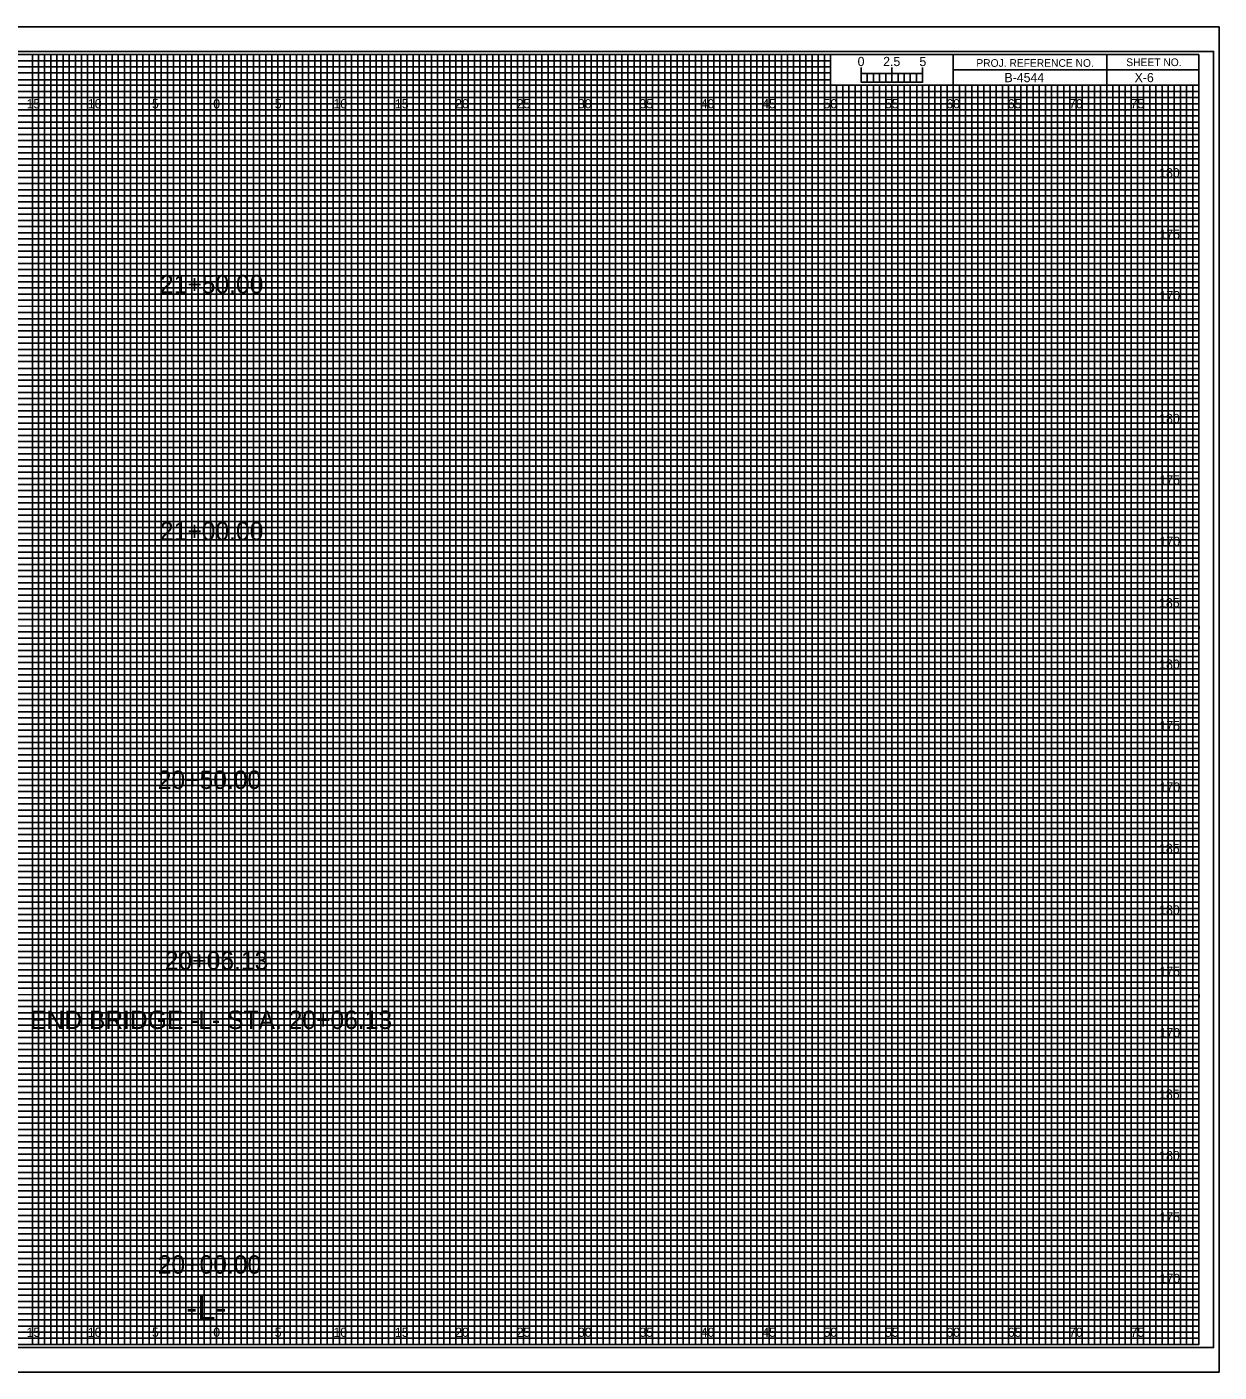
# Model space of a CAD drawing. Extents: x -7 to 162, y -2 to 767.
# Drawn here: x 64.6 to 161.7, y 547.8 to 657.2 of the extents above; entities that cross this region are included whole.
import ezdxf

# ---------------------------------------------------------------- set-up
doc = ezdxf.new("R2010")
doc.units = 0
for name, color, linetype in [('Exist CMT Pavement', 7, 'Continuous'), ('Exist Cross Section Cell', 7, 'Continuous'), ('Exist XS Ground Line', 7, 'Continuous'), ('Prop CMT Pvmt Course 1', 7, 'Continuous'), ('Prop CMT Pvmt Course 1 Wedge', 7, 'Continuous'), ('Prop CMT Pvmt Course 2', 7, 'Continuous'), ('Prop CMT Pvmt Course 2 Wedge', 7, 'Continuous'), ('Prop CMT Pvmt Course 3', 7, 'Continuous'), ('Prop CMT Pvmt Course 3 Wedge', 7, 'Continuous'), ('Prop CMT Pvmt Surface', 7, 'Continuous'), ('Prop CMT Pvmt Surface Shoulder', 7, 'Continuous'), ('Prop CMT Shld Paved Course 1', 7, 'Continuous'), ('Prop CMT Shld Paved Course 2', 7, 'Continuous'), ('Prop CMT Shld Paved Course 3', 7, 'Continuous'), ('Prop CMT Slope Grass', 7, 'Continuous'), ('Prop CMT Subgrade Earthwork', 7, 'Continuous'), ('Scratch_Level_0', 7, 'Continuous')]:
    doc.layers.add(name, color=color, linetype=linetype)

msp = doc.modelspace()

# ---------------------------------------------------------------- linework, layer by layer
at = {"layer": 'Prop CMT Pvmt Course 1'}
for p, q in [((0, 654.5), (130, 654.5)), ((130, 653.99), (0, 653.99)), ((130, 654.5), (130, 653.99)), ((0, 653.5), (130, 653.5)), ((130, 652.95), (0, 652.95)), ((130, 653.5), (130, 652.95)), ((0, 652), (160, 652))]:
    msp.add_line(p, q, dxfattribs=at)
for points in [[(0, 651.5), (135, 651.5), (160, 651.5), (160, 651), (0, 651)], [(0, 650.5), (160, 650.5), (160, 649.5), (0, 649.5)], [(0, 649), (160, 649), (160, 648.5), (0, 648.49)], [(0, 648), (160, 648), (160, 647), (0, 647)], [(0, 646.5), (160, 646.5), (160, 646), (0, 646)], [(0, 645.5), (160, 645.5), (160, 644.5), (0, 644.5)], [(0, 644), (160, 644), (160, 643.5), (0, 643.5)], [(0, 643), (160, 643), (160, 642), (0, 642)], [(0, 641.5), (160, 641.5), (160, 641), (0, 641)], [(0, 640.5), (160, 640.5), (160, 639.5), (0, 639.5)], [(0, 639), (160, 639), (160, 638.5), (0, 638.5)], [(0, 638), (160, 638), (160, 636.98), (160, 636.5), (160, 636), (0, 636)], [(0, 637), (160, 637), (160, 636.5), (0, 636.5)], [(0, 635.5), (160, 635.5), (160, 634.5), (0, 634.51)], [(0, 634.51), (160, 634.5), (160, 634), (0, 634)], [(0, 633.5), (160, 633.5), (160, 633), (0, 633)], [(0, 632), (160, 632), (160, 631.5), (0, 631.5)], [(0, 631), (160, 631), (160, 630.5), (0, 630.5)], [(-0.04, 629.45), (160, 629.45), (160, 628.94), (-0.04, 628.94)], [(0, 628.5), (160, 628.5), (160, 628), (0, 628)], [(0, 627), (160, 627), (160, 626.5), (0, 626.5)], [(0, 626), (160, 626), (160, 625.5), (0, 625.5)], [(0, 624.5), (160, 624.5), (160, 624), (0, 624)], [(0, 623.5), (160, 623.5), (160, 623), (0, 623)], [(0, 622), (160, 622), (160, 621.5), (0, 621.5)], [(0, 621), (160, 621), (160, 620.5), (0, 620.5)], [(0, 619.5), (160, 619.5), (160, 618.99), (0, 619)], [(0, 618.5), (160, 618.5), (160, 618), (0, 618)], [(0, 617), (160, 617), (160, 616.5), (0, 616.5)], [(0, 616), (160, 616), (160, 615.5), (0, 615.5)], [(0, 614.5), (160, 614.5), (160, 614), (0, 614)], [(0, 613.5), (160, 613.5), (160, 613), (0, 613)], [(0, 612), (160, 612), (160, 611.5), (0, 611.5)], [(0, 611), (160, 611), (160, 610.5), (0, 610.5)], [(0, 609.5), (160, 609.5), (160, 609), (0, 609)], [(0, 608.5), (160.03, 608.46), (160, 608), (0, 608)], [(0, 607), (160, 607), (160, 606.5), (0, 606.5)], [(0, 606), (160, 606), (160, 605.5), (0, 605.5)], [(0, 604.5), (160, 604.5), (160, 604), (0, 604)], [(0, 603.5), (160, 603.5), (160, 603), (0, 603)], [(0, 602), (160, 602), (160, 601.5), (0, 601.5)], [(0, 601), (160, 601), (160, 600.5), (0, 600.5)], [(0, 599.5), (160, 599.5), (160, 599), (0, 599)], [(0, 598.5), (160, 598.5), (160, 598), (0, 598)], [(0, 597), (160, 597), (160, 596.5), (0, 596.5)], [(0, 596), (160, 596), (160, 595.5), (0, 595.5)], [(0, 594.5), (160, 594.5), (160, 594), (0, 594)], [(0, 593.5), (160, 593.5), (160, 593), (0, 593)], [(0, 592), (160, 592), (160, 591.5), (0, 591.5)], [(0, 591), (160, 591), (160, 590.5), (0, 590.5)], [(0, 589.5), (160, 589.5), (160, 588.99), (0, 589)], [(0, 588.5), (160, 588.5), (160, 588), (0, 588)], [(0, 587), (160, 587), (160, 586.5), (0, 586.5)], [(0, 586), (160, 586), (160, 585.5), (0, 585.5)], [(0, 584.5), (160, 584.5), (160, 584), (0, 584)], [(0, 583.5), (160, 583.5), (160, 583), (0, 583)], [(0, 582), (160, 582), (160, 581.5), (0, 581.5)], [(0, 581), (160, 581), (160, 580.5), (0, 580.5)], [(0, 579.5), (160, 579.5), (160, 579), (0, 579)], [(0, 578.5), (160.03, 578.46), (160, 578), (0, 578)], [(0, 577), (160, 577), (160, 576.5), (0, 576.5)], [(0, 576), (160, 576), (160, 575.5), (0, 575.5)], [(0, 574.5), (160, 574.5), (160, 574), (0, 574)], [(0, 573.5), (160, 573.5), (160, 573), (0, 573)], [(0, 572), (160, 572), (160, 571.5), (0, 571.5)], [(0, 571), (160, 571), (160, 570.5), (0, 570.5)], [(0, 569.5), (160, 569.5), (160, 569), (0, 569)], [(0, 568.5), (160, 568.5), (160, 568), (0, 568)], [(0, 567), (160, 567), (160, 566.5), (0, 566.5)], [(0, 566), (160, 566), (160, 565.5), (0, 565.5)], [(0, 564.5), (160, 564.5), (160, 564), (0, 564)], [(0, 563.5), (160, 563.5), (160, 563), (0, 563)], [(0, 562), (160, 562), (160, 561.5), (0, 561.5)], [(0, 561), (160, 561), (160, 560.5), (0, 560.5)], [(0, 559.5), (160, 559.5), (160, 559), (0, 559)], [(0, 558.5), (160, 558.5), (160, 558), (0, 558)], [(0, 557), (160, 557), (160, 556.5), (0, 556.5)], [(0, 556), (160, 556), (160, 555.5), (0, 555.5)], [(0, 554.5), (160, 554.5), (160, 554), (0, 554)], [(0, 553.5), (160, 553.5), (160, 553), (0, 553)], [(0, 552), (160, 552), (160, 551.5), (0, 551.5)], [(0, 551), (160, 551), (160, 550.5), (0, 550.5)]]:
    msp.add_lwpolyline(points, dxfattribs=at)
at = {"layer": 'Prop CMT Pvmt Course 2'}
for p, q in [((65, 550), (65, 655)), ((70, 550), (70, 655)), ((75, 550), (75, 655)), ((80, 550), (80, 655)), ((85, 550), (85, 655)), ((90, 550), (90, 655)), ((95, 550), (95, 655)), ((100, 550), (100, 655)), ((105, 550), (105, 655)), ((110, 550), (110, 655)), ((115, 550), (115, 655)), ((120, 550), (120, 655)), ((125, 550), (125, 655)), ((130, 550), (130, 652.34)), ((135, 550), (135, 652.34)), ((140, 550), (140, 652.34)), ((145, 550), (145, 652.34)), ((150, 550), (150, 652.34)), ((155, 550), (155, 652.34)), ((0, 650), (160, 650)), ((0, 645), (160, 645)), ((0, 640), (160, 640)), ((0, 635), (160, 635)), ((0, 630), (160, 630)), ((0, 625), (160, 625)), ((0, 620), (160, 620)), ((0, 615), (160, 615)), ((0, 610), (160, 610)), ((0, 605), (160, 605)), ((0, 600), (160, 600)), ((0, 595), (160, 595)), ((0, 590), (160, 590)), ((0, 585), (160, 585)), ((0, 580), (160, 580)), ((0, 575), (160, 575)), ((0, 570), (160, 570)), ((0, 565), (160, 565)), ((0, 560), (160, 560)), ((0, 555), (160, 555))]:
    msp.add_line(p, q, dxfattribs=at)
at = {"layer": 'Prop CMT Pvmt Course 3'}
for p, q in [((161.65, 657.25), (-6.7, 657.25)), ((-6.7, 547.75), (161.65, 547.75))]:
    msp.add_line(p, q, dxfattribs=at)
at = {"layer": 'Prop CMT Pvmt Surface Shoulder'}
for points in [[(62.5, 550), (67.5, 550), (67.5, 655), (72.5, 655), (72.5, 550), (77.5, 550), (77.5, 655), (82.5, 655), (82.5, 550), (87.5, 550), (87.5, 655), (92.5, 655), (92.5, 550), (97.5, 550), (97.5, 655), (102.5, 655), (102.5, 550), (107.5, 550), (107.5, 655), (112.5, 655), (112.5, 550), (117.5, 550), (117.5, 655), (122.5, 655), (122.5, 550), (127.5, 550), (127.5, 655), (129.97, 655), (130, 655), (130, 652.5), (132.5, 652.5), (132.5, 550), (137.5, 550), (137.5, 652.5), (142.5, 652.5), (142.5, 550), (147.5, 550), (147.5, 652.5), (152.5, 652.5), (152.5, 550), (157.5, 550), (157.5, 652.5)], [(0, 652.5), (137.5, 652.5)], [(0, 642.5), (160, 642.5), (160, 647.5), (0, 647.5)], [(0, 632.5), (160, 632.5), (160, 637.5), (0, 637.5)], [(0, 622.5), (160, 622.5), (160, 627.5), (0, 627.5)], [(0, 612.5), (160, 612.5), (160, 617.5), (0, 617.5)], [(0, 602.5), (160, 602.5), (160, 607.5), (0, 607.5)], [(0, 592.5), (160, 592.5), (160, 597.5), (0, 597.5)], [(0, 582.5), (160, 582.5), (160, 587.5), (0, 587.5)], [(0, 572.5), (160, 572.5), (160, 577.5), (0, 577.5)], [(0, 562.5), (160, 562.5), (160, 567.5), (0, 567.5)], [(0, 552.5), (160, 552.5), (160, 557.5), (0, 557.5)]]:
    msp.add_lwpolyline(points, dxfattribs=at)
at = {"layer": 'Prop CMT Shld Paved Course 1'}
for p, q in [((132.5, 652.75), (132.5, 653.95)), ((132.5, 653.45), (132.5, 653.95)), ((135, 652.75), (135, 653.95)), ((137.5, 652.75), (137.5, 653.95)), ((137.5, 653.45), (137.5, 653.95))]:
    msp.add_line(p, q, dxfattribs=at)
for points in [[(137.5, 653.45), (132.5, 653.45), (132.5, 652.75), (137.5, 652.75)], [(132.5, 653.45), (133, 653.45), (133, 652.75), (132.5, 652.75)], [(133.5, 653.45), (134, 653.45), (134, 652.75), (133.5, 652.75)], [(134.5, 653.45), (135, 653.45), (135, 652.75), (134.5, 652.75)], [(135.5, 653.45), (136, 653.45), (136, 652.75), (135.5, 652.75)], [(136.5, 653.45), (137, 653.45), (137, 652.75), (136.5, 652.75)]]:
    msp.add_lwpolyline(points, close=True, dxfattribs=at)
at = {"layer": 'Prop CMT Shld Paved Course 2'}
msp.add_lwpolyline([(-6.7, 547.75), (161.65, 547.75), (161.65, 657.25), (-6.7, 657.25)], close=True, dxfattribs=at)
at = {"layer": 'Prop CMT Shld Paved Course 3'}
msp.add_lwpolyline([(-5.4, 549.75), (161.2, 549.75), (161.2, 655.25), (-5.4, 655.25)], close=True, dxfattribs=at)
at = {"layer": 'Prop CMT Slope Grass'}
for p, q in [((133.5, 652.5), (133, 652.5)), ((133, 652.5), (133, 550)), ((133.5, 550), (133.5, 652.5)), ((134.5, 652.5), (134, 652.5)), ((134, 652.5), (134, 550)), ((134.5, 550), (134.5, 652.5)), ((133, 550), (132.5, 550)), ((134, 550), (133.5, 550))]:
    msp.add_line(p, q, dxfattribs=at)
for points in [[(65, 550), (65.5, 550), (65.5, 655), (66, 655), (66, 550)], [(66, 550), (66.5, 550), (66.5, 655), (67, 655), (67, 550)], [(67.5, 550), (68, 550), (68, 655), (68.5, 655), (68.5, 550)], [(68.5, 550), (69, 550), (69, 655), (69.5, 655), (69.5, 550)], [(70, 550), (70.5, 550), (70.5, 655), (71, 655), (71, 550)], [(71, 550), (71.5, 550), (71.5, 655), (72, 655), (72, 550)], [(72.5, 550), (73, 550), (73, 655), (73.5, 655), (73.5, 550)], [(73.5, 550), (74, 550), (74, 655), (74.5, 655), (74.5, 550)], [(75, 550), (75.5, 550), (75.5, 655), (76, 655), (76, 550)], [(76, 550), (76.5, 550), (76.5, 655), (77, 655), (77, 550)], [(77.5, 550), (78, 550), (78, 655), (78.5, 655), (78.5, 550)], [(78.5, 550), (79, 550), (79, 655), (79.5, 655), (79.5, 550)], [(80, 550), (80.5, 550), (80.5, 655), (81, 655), (81, 550)], [(81, 550), (81.5, 550), (81.5, 655), (82, 655), (82, 550)], [(82.5, 550), (83, 550), (83, 655), (83.5, 655), (83.5, 550)], [(83.5, 550), (84, 550), (84, 655), (84.5, 655), (84.5, 550)], [(85, 550), (85.5, 550), (85.5, 655), (86, 655), (86, 550)], [(86, 550), (86.5, 550), (86.5, 655), (87, 655), (87, 550)], [(87.5, 550), (88, 550), (88, 655), (88.5, 655), (88.5, 550)], [(88.5, 550), (89, 550), (89, 655), (89.5, 655), (89.5, 550)], [(90, 550), (90.5, 550), (90.5, 655), (91, 655), (91, 550)], [(91, 550), (91.5, 550), (91.5, 655), (92, 655), (92, 550)], [(92.5, 550), (93, 550), (93, 655), (93.5, 655), (93.5, 550)], [(93.5, 550), (94, 550), (94, 655), (94.5, 655), (94.5, 550)], [(95, 550), (95.5, 550), (95.5, 655), (96, 655), (96, 550)], [(96, 550), (96.5, 550), (96.5, 655), (97, 655), (97, 550)], [(97.5, 550), (98, 550), (98, 655), (98.5, 655), (98.5, 550)], [(98.5, 550), (99, 550), (99, 655), (99.5, 655), (99.5, 550)], [(100, 550), (100.5, 550), (100.5, 655), (101, 655), (101, 550)], [(101, 550), (101.5, 550), (101.5, 655), (102, 655), (102, 550)], [(102.5, 550), (103, 550), (103, 655), (103.5, 655), (103.5, 550)], [(103.5, 550), (104, 550), (104, 655), (104.5, 655), (104.5, 550)], [(105, 550), (105.5, 550), (105.5, 655), (106, 655), (106, 550)], [(106, 550), (106.5, 550), (106.5, 655), (107, 655), (107, 550)], [(107.5, 550), (108, 550), (108, 655), (108.5, 655), (108.5, 550)], [(108.5, 550), (109, 550), (109, 655), (109.5, 655), (109.5, 550)], [(110, 550), (110.5, 550), (110.5, 655), (111, 655), (111, 550)], [(111, 550), (111.5, 550), (111.5, 655), (112, 655), (112, 550)], [(112.5, 550), (113, 550), (113, 655), (113.5, 655), (113.5, 550)], [(113.5, 550), (114, 550), (114, 655), (114.5, 655), (114.5, 550)], [(115, 550), (115.5, 550), (115.5, 655), (116, 655), (116, 550)], [(116, 550), (116.5, 550), (116.5, 655), (117, 655), (117, 550)], [(117.5, 550), (118, 550), (118, 655), (118.5, 655), (118.5, 550)], [(118.5, 550), (119, 550), (119, 655), (119.5, 655), (119.5, 550)], [(120, 550), (120.5, 550), (120.5, 655), (121, 655), (121, 550)], [(121, 550), (121.5, 550), (121.5, 655), (122, 655), (122, 550)], [(122.5, 550), (123, 550), (123, 655), (123.5, 655), (123.5, 550)], [(123.5, 550), (124, 550), (124, 655), (124.5, 655), (124.5, 550)], [(125, 550), (125.5, 550), (125.5, 655), (126, 655), (126, 550)], [(126, 550), (126.5, 550), (126.5, 655), (127, 655), (127, 550)], [(127.5, 550), (128, 550), (128, 655), (128.5, 655), (128.5, 550)], [(128.5, 550), (129, 550), (129, 655), (129.5, 655), (129.5, 550)], [(130, 550), (130.5, 550), (130.5, 652.5), (131.01, 652.5), (131.01, 550)], [(131, 550), (131.5, 550), (131.5, 652.5), (132, 652.5), (132, 550)], [(135, 550), (135.49, 550), (135.49, 652.5), (136, 652.5), (136, 550)], [(136, 550), (136.5, 550), (136.5, 652.5), (137.03, 652.5), (137.03, 550)], [(137.5, 550), (138, 550), (138, 652.5), (138.5, 652.5), (138.5, 550)], [(138.5, 550), (139, 550), (139, 652.5), (139.5, 652.5), (139.5, 550)], [(140, 550), (140.5, 550), (140.5, 652.5), (141, 652.5), (141, 550)], [(141, 550), (141.5, 550), (141.5, 652.5), (142, 652.5), (142, 550)], [(142.5, 550), (143, 550), (143, 652.5), (143.5, 652.5), (143.5, 550)], [(143.5, 550), (144, 550), (144, 652.5), (144.5, 652.5), (144.5, 550)], [(145, 550), (145.5, 550), (145.5, 652.5), (146, 652.5), (146, 550)], [(146, 550), (146.5, 550), (146.5, 652.5), (147, 652.5), (147, 550)], [(147.5, 550), (148, 550), (148, 652.5), (148.5, 652.5), (148.5, 550)], [(148.5, 550), (149, 550), (149, 652.5), (149.5, 652.5), (149.5, 550)], [(150, 550), (150.5, 550), (150.5, 652.5), (151, 652.5), (151, 550)], [(151, 550), (151.5, 550), (151.5, 652.5), (152, 652.5), (152, 550)], [(152.5, 550), (153, 550), (153, 652.5), (153.5, 652.5), (153.5, 550)], [(153.5, 550), (154, 550), (154, 652.5), (154.5, 652.5), (154.5, 550)], [(155, 550), (155.5, 550), (155.5, 652.5), (156, 652.5), (156, 550)], [(156, 550), (156.5, 550), (156.5, 652.5), (157, 652.5), (157, 550)], [(157.5, 550), (158, 550), (158, 652.5), (158.5, 652.5), (158.5, 550)], [(158.5, 550), (159, 550), (159, 652.5), (159.5, 652.5), (159.5, 550)]]:
    msp.add_lwpolyline(points, dxfattribs=at)
at = {"layer": 'Prop CMT Subgrade Earthwork'}
for p, q in [((152.5, 655), (152.5, 652.5)), ((152.5, 652.5), (152.5, 655)), ((160, 653.75), (140, 653.75)), ((140, 653.75), (140, 652.5)), ((140, 652.5), (160, 652.5))]:
    msp.add_line(p, q, dxfattribs=at)
for points in [[(160, 655), (0, 655), (0, 550), (160, 550)], [(140, 655), (130, 655), (130, 652.51), (140, 652.51)], [(160, 655), (140, 655), (140, 652.5), (160, 652.5)]]:
    msp.add_lwpolyline(points, close=True, dxfattribs=at)
at = {"layer": 'Scratch_Level_0'}
for p, q in [((65, 655), (60, 655)), ((65, 550), (65, 655)), ((75, 655), (70, 655)), ((70, 655), (70, 550)), ((75, 550), (75, 655)), ((85, 655), (80, 655)), ((80, 655), (80, 550)), ((85, 550), (85, 655)), ((95, 655), (90, 655)), ((90, 655), (90, 550)), ((95, 550), (95, 655)), ((105, 655), (100, 655)), ((100, 655), (100, 550)), ((105, 550), (105, 655)), ((115, 655), (110, 655)), ((110, 655), (110, 550)), ((115, 550), (115, 655)), ((125, 655), (120, 655)), ((120, 655), (120, 550)), ((125, 550), (125, 655)), ((130, 655), (130, 550)), ((135, 550), (135, 652.5)), ((145, 652.5), (140, 652.5)), ((140, 652.5), (140, 550)), ((145, 550), (145, 652.5)), ((155, 652.5), (150, 652.5)), ((150, 652.5), (150, 550)), ((155, 550), (155, 652.5)), ((70, 550), (65, 550)), ((80, 550), (75, 550)), ((90, 550), (85, 550)), ((100, 550), (95, 550)), ((110, 550), (105, 550)), ((120, 550), (115, 550)), ((130, 550), (125, 550)), ((140, 550), (135, 550)), ((150, 550), (145, 550)), ((160, 550), (155, 550)), ((160, 550), (160, 550))]:
    msp.add_line(p, q, dxfattribs=at)
for points in [[(0, 650), (160, 650), (160, 645), (0, 645)], [(0, 640), (160, 640), (160, 635), (0, 635)], [(0, 630), (160, 630), (160, 625), (0, 625)], [(0, 620), (160, 620), (160, 615), (0, 615)], [(0, 610), (160, 610), (160, 605), (0, 605)], [(0, 600), (160, 600), (160, 595), (0, 595)], [(0, 590), (160, 590), (160, 585), (0, 585)], [(0, 580), (160, 580), (160, 575), (0, 575)], [(0, 570), (160, 570), (160, 565), (0, 565)], [(0, 560), (160, 560), (160, 555), (0, 555)]]:
    msp.add_lwpolyline(points, dxfattribs=at)

# ---------------------------------------------------------------- texts
at = {"layer": 'Exist CMT Pavement'}
msp.add_text('B-4544', height=0.75, dxfattribs=at).set_placement((144.17, 652.75))
at = {"layer": 'Exist Cross Section Cell'}
for s, p in [('15', (64.53, 650.62)), ('10', (69.52, 650.62)), ('5', (74.74, 650.62)), ('0', (79.73, 650.62)), ('0', (79.73, 650.62)), ('5', (84.74, 650.62)), ('10', (89.52, 650.62)), ('15', (94.53, 650.62)), ('20', (99.43, 650.62)), ('25', (104.44, 650.62)), ('30', (109.43, 650.62)), ('35', (114.44, 650.62)), ('40', (119.43, 650.62)), ('45', (124.44, 650.62)), ('50', (129.43, 650.62)), ('55', (134.44, 650.62)), ('60', (139.43, 650.62)), ('65', (144.44, 650.62)), ('70', (149.43, 650.62)), ('75', (154.44, 650.62)), ('15', (64.53, 550.62)), ('10', (69.52, 550.62)), ('5', (74.74, 550.62)), ('0', (79.73, 550.62)), ('0', (79.73, 550.62)), ('5', (84.74, 550.62)), ('10', (89.52, 550.62)), ('15', (94.53, 550.62)), ('20', (99.43, 550.62)), ('25', (104.44, 550.62)), ('30', (109.43, 550.62)), ('35', (114.44, 550.62)), ('40', (119.43, 550.62)), ('45', (124.44, 550.62)), ('50', (129.43, 550.62)), ('55', (134.44, 550.62)), ('60', (139.43, 550.62)), ('65', (144.44, 550.62)), ('70', (149.43, 550.62)), ('75', (154.44, 550.62))]:
    msp.add_text(s, height=0.75, dxfattribs=at).set_placement(p)
at = {"layer": 'Exist XS Ground Line'}
for s, p in [('2.5', (134.29, 654.06)), ('5', (137.24, 654.06))]:
    msp.add_text(s, height=0.75, dxfattribs=at).set_placement(p)
at = {"layer": 'Prop CMT Pvmt Course 1 Wedge'}
for s, p in [('180', (156.77, 645)), ('175', (156.79, 640)), ('170', (156.8, 635)), ('180', (156.77, 625)), ('175', (156.79, 620)), ('170', (156.8, 615)), ('185', (156.76, 610)), ('180', (156.77, 605)), ('175', (156.79, 600)), ('170', (156.8, 595)), ('185', (156.76, 590)), ('180', (156.77, 585)), ('175', (156.79, 580)), ('170', (156.8, 575)), ('185', (156.76, 570)), ('180', (156.77, 565)), ('175', (156.79, 560)), ('170', (156.8, 555))]:
    msp.add_text(s, height=0.75, dxfattribs=at).set_placement(p)
at = {"layer": 'Prop CMT Pvmt Course 2 Wedge'}
for s, p in [('21+50.00', (75.39, 635.56)), ('21+00.00', (75.39, 615.46)), ('20+50.00', (75.21, 595.22)), ('20+06.13', (75.79, 580.5)), ('END BRIDGE -L- STA. 20+06.13', (64.81, 575.68)), ('20+00.00', (75.21, 555.76))]:
    msp.add_text(s, height=1.5, dxfattribs=at).set_placement(p)
at = {"layer": 'Prop CMT Pvmt Course 3 Wedge'}
msp.add_text('X-6', height=0.75, dxfattribs=at).set_placement((154.77, 652.75))
at = {"layer": 'Prop CMT Pvmt Surface'}
msp.add_text('-L-', height=2, dxfattribs=at).set_placement((77.53, 552))
at = {"layer": 'Prop CMT Shld Paved Course 1'}
msp.add_text('0', height=0.75, dxfattribs=at).set_placement((132.21, 654.06))
at = {"layer": 'Prop CMT Subgrade Earthwork'}
for s, p in [('PROJ. REFERENCE NO.', (141.88, 654)), ('SHEET NO.', (154.09, 654.06))]:
    msp.add_text(s, height=0.625, dxfattribs=at).set_placement(p)

doc.saveas('drawing.dxf')
